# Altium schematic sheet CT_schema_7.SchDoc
size 254 x 194 mm
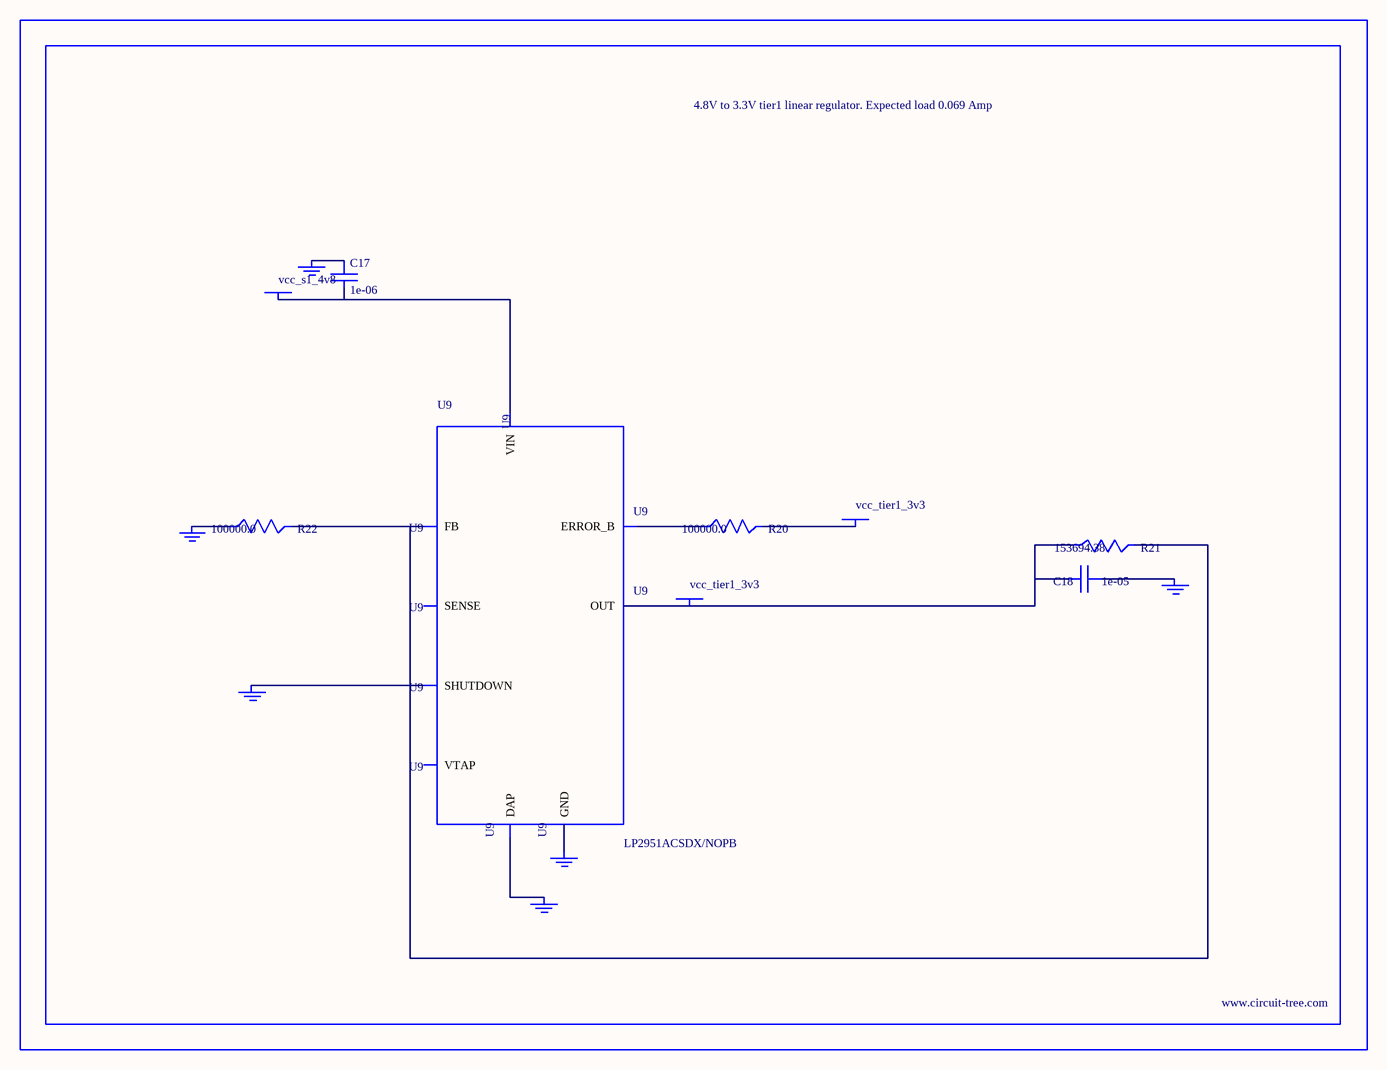
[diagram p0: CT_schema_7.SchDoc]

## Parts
BORDER6  (no value)
C17  1e-06  [C0603]
C18  1e-05  [C1210]
GND_INSTANCE_6_0  (no value)
GND_INSTANCE_6_1  (no value)
GND_INSTANCE_6_2  (no value)
GND_INSTANCE_6_3  (no value)
GND_INSTANCE_6_4  (no value)
GND_INSTANCE_6_5  (no value)
POWER_INSTANCE_6_0  vcc_tier1_3v3
POWER_INSTANCE_6_1  vcc_s1_4v8
POWER_INSTANCE_6_2  vcc_tier1_3v3
R20  100000.0  [R0603]
R21  153694.38  [R0603]
R22  100000.0  [R0603]
U9  LP2951ACSDX/NOPB  [WSON-8]

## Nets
NetC17_1: C17.1 GND_INSTANCE_6_3.0(GND)
NetC17_2: C17.2 POWER_INSTANCE_6_1.0(PWR) U9.8(VIN)
NetC18_1: C18.1 GND_INSTANCE_6_0.0(GND)
NetC18_2: C18.2 POWER_INSTANCE_6_2.0(PWR) R21.1 U9.1(OUT)
NetGND_INSTANCE_6_1_0: GND_INSTANCE_6_1.0(GND) U9.3(SHUTDOWN)
NetGND_INSTANCE_6_2_0: GND_INSTANCE_6_2.0(GND) R22.1
NetGND_INSTANCE_6_4_0: GND_INSTANCE_6_4.0(GND) U9.PAD(DAP)
NetGND_INSTANCE_6_5_0: GND_INSTANCE_6_5.0(GND) U9.4(GND)
NetPOWER_INSTANCE_6_0_0: POWER_INSTANCE_6_0.0(PWR) R20.2
NetR20_1: R20.1 U9.5(ERROR_B)
NetR21_2: R21.2 R22.2 U9.7(FB)

Not connected (* = marked no-connect by the designer): U9 2(SENSE) 6(VTAP)

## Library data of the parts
BORDER6 = BORDER_PAGE6
C17 = C0603C105K3RACTU
C18 = GRM32DR61E106MA12L
GND_INSTANCE_6_0-GND_INSTANCE_6_5 = GND
POWER_INSTANCE_6_0-POWER_INSTANCE_6_2 = PWR
R20 R22 = RC0603JR-07100KL
R21 = R21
